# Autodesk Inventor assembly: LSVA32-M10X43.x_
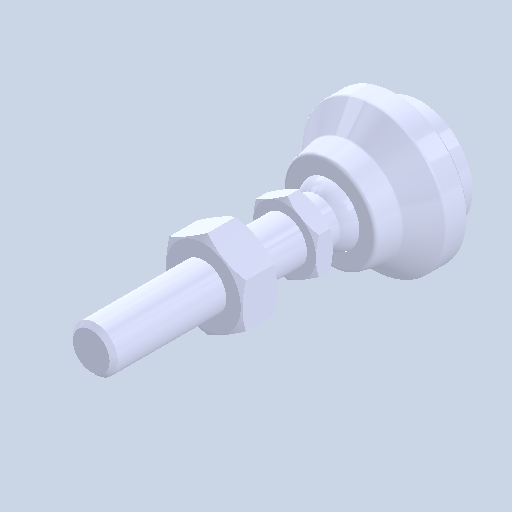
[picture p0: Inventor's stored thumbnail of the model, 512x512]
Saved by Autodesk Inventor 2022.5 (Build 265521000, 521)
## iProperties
Created: 2024-08
Part Number: LSVA32-M10X43.x_
Document SubType Name: Assembly
Designer: ImaoCorp
Author: ImaoCorp
Sending System: SOLIDWORKS 2022-2022290
MC: AMD64
MC_MODEL: Intel64 Family 6 Model 60 Stepping 3, GenuineIntel
OS: Windows_NT
FRU: Parasolid Version 33.1, build 260,  4-25-2022
FORMAT: text
GUISE: transmit
KEY: FILELSVA32-M10X43.x_t
DATE: Fri Aug 23 16:06:19 2024
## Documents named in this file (4)
- X:\14_SW2022-Inv2022\06_2024-10新製品(SME)\ELS_データ\l\lsva32-m10x43\LSVA32-M10X43.x_.iam
- X:\14_SW2022-Inv2022\06_2024-10新製品(SME)\ELS_データ\l\lsva32-m10x43\LSVA32-M10X43_01.ipt
- X:\14_SW2022-Inv2022\06_2024-10新製品(SME)\ELS_データ\l\lsva32-m10x43\LSVA32-M10X43_02.ipt
- X:\14_SW2022-Inv2022\06_2024-10新製品(SME)\ELS_データ\l\lsva32-m10x43\LSVA32-M10X43_03.ipt
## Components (3 placed, 3 different names)
1. LSVA32-M10X43_01
2. LSVA32-M10X43_02
3. LSVA32-M10X43_03
